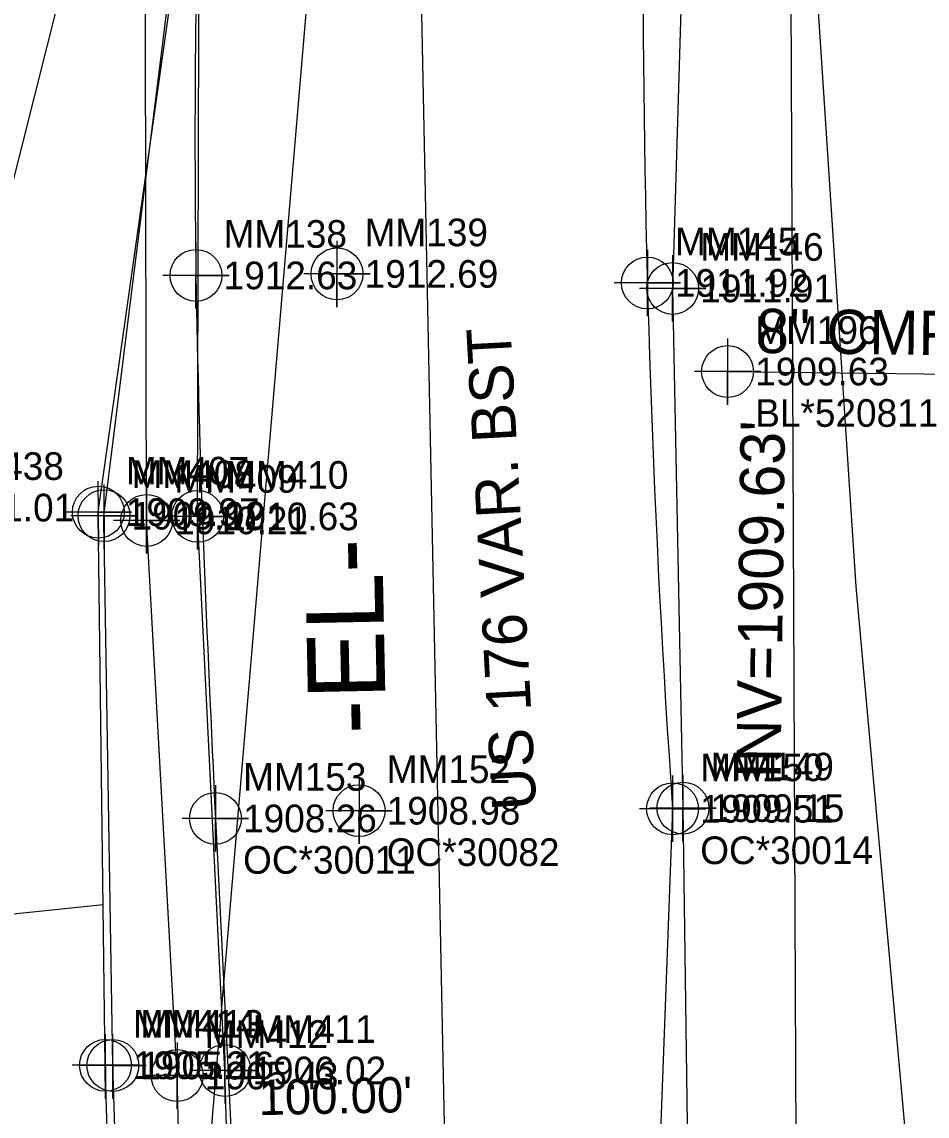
# Model space of a CAD drawing. Extents: x 1004514 to 1005247, y 553695 to 554706.
# Drawn here: x 1004985.3 to 1005067.1, y 554027.6 to 554126.5 of the extents above; entities that cross this region are included whole.
import ezdxf

# ---------------------------------------------------------------- set-up
doc = ezdxf.new("R2010")
doc.units = 0
for name, color, linetype in [('COGO Default Chain', 7, 'Continuous'), ('Default Symbol Cogo Elevation', 7, 'Continuous'), ('Default Symbol Cogo Number', 7, 'Continuous'), ('Exist DTM Crownline Cogo Comment', 7, 'Continuous'), ('Exist DTM Crownline Cogo Elevation', 7, 'Continuous'), ('Exist DTM Crownline Cogo Number', 7, 'Continuous'), ('Exist DTM Crownline Cogo Point CELL', 7, 'Continuous'), ('Exist Guardrail', 7, 'Continuous'), ('Exist Guardrail Cogo Elevation', 7, 'Continuous'), ('Exist Guardrail Cogo Number', 7, 'Continuous'), ('Exist Guardrail Cogo Point CELL', 7, 'Continuous'), ('Exist Horizontal Alignment', 7, 'Continuous'), ('Exist Horizontal Alignment Direction Label', 7, 'Continuous'), ('Exist Right of Way Width CELL', 7, 'Continuous'), ('Exist Roads EOP', 7, 'Continuous'), ('Exist Roads EOP Cogo Comment', 7, 'Continuous'), ('Exist Roads EOP Cogo Elevation', 7, 'Continuous'), ('Exist Roads EOP Cogo Number', 7, 'Continuous'), ('Exist Roads EOP Cogo Point CELL', 7, 'Continuous'), ('Exist Roads EOP Text', 7, 'Continuous'), ('Exist Structure Minor Pipes CMP 8 Inch', 7, 'Continuous'), ('Exist Structure Minor Pipes CMP 8 Inch Cogo Comment', 7, 'Continuous'), ('Exist Structure Minor Pipes CMP 8 Inch Cogo Elevation', 7, 'Continuous'), ('Exist Structure Minor Pipes CMP 8 Inch Cogo Number', 7, 'Continuous'), ('Exist Structure Minor Pipes CMP 8 Inch Cogo Point CELL', 7, 'Continuous'), ('Exist Structure Minor Pipes CMP 8 Inch Invert', 7, 'Continuous'), ('Exist Structure Minor Pipes CMP 8 Inch Text', 7, 'Continuous'), ('Exist Utilities Telephone UG Conduit SUE LOS B', 7, 'Continuous'), ('Exist Utilities Telephone UG Conduit SUE LOS B Cogo Elevation', 7, 'Continuous'), ('Exist Utilities Telephone UG Conduit SUE LOS B Cogo Number', 7, 'Continuous'), ('Exist Utilities Telephone UG Conduit SUE LOS B Cogo Point CELL', 7, 'Continuous'), ('Exist Utilities Telephone UG Conduit SUE LOS B Leader', 7, 'Continuous'), ('Exist Utilities Telephone UG FO SUE LOS C', 7, 'Continuous'), ('Exist Utilities Telephone UG FO SUE LOS C Cogo Elevation', 7, 'Continuous'), ('Exist Utilities Telephone UG FO SUE LOS C Cogo Number', 7, 'Continuous'), ('Exist Utilities Telephone UG FO SUE LOS C Cogo Point CELL', 7, 'Continuous'), ('Exist Vegetation Woods Line', 7, 'Continuous'), ('Old_Level_3', 7, 'Continuous'), ('Scratch_Level_3', 7, 'Continuous')]:
    doc.layers.add(name, color=color, linetype=linetype)

msp = doc.modelspace()

# ---------------------------------------------------------------- linework, layer by layer
at = {"layer": 'COGO Default Chain'}
for p, q in [((1004974.9, 553701.543), (1005020.282, 554237.182)), ((1005024.623, 553970.464), (1005021.236, 554137.94))]:
    msp.add_line(p, q, dxfattribs=at)
at = {"layer": 'Exist DTM Crownline Cogo Point CELL'}
for points in [[(1005013.771, 554106.753), (1005013.771, 554100.753), (1005013.771, 554103.753), (1005016.771, 554103.753), (1005010.771, 554103.753)], [(1005015.769, 554058.214), (1005015.769, 554052.214), (1005015.769, 554055.214), (1005018.769, 554055.214), (1005012.769, 554055.214)]]:
    msp.add_lwpolyline(points, dxfattribs=at)
for centre in [(1005013.771, 554103.753), (1005015.769, 554055.214)]:
    msp.add_circle(centre, 2.344, dxfattribs=at)
at = {"layer": 'Exist Guardrail'}
msp.add_lwpolyline([(1005077.879, 554238.993), (1005058.749, 554204.287), (1005049.992, 554175.596), (1005045.293, 554142.756), (1005044.111, 554102.438), (1005045.04, 554055.452), (1005045.63, 554011.474), (1005045.274, 553965.154), (1005039.583, 553916.738), (1005028.889, 553873.019)], dxfattribs=at)
at = {"layer": 'Exist Guardrail Cogo Point CELL'}
for points in [[(1005044.111, 554105.438), (1005044.111, 554099.438), (1005044.111, 554102.438), (1005047.111, 554102.438), (1005041.111, 554102.438)], [(1005045.04, 554058.452), (1005045.04, 554052.452), (1005045.04, 554055.452), (1005048.04, 554055.452), (1005042.04, 554055.452)]]:
    msp.add_lwpolyline(points, dxfattribs=at)
for centre in [(1005044.111, 554102.438), (1005045.04, 554055.452)]:
    msp.add_circle(centre, 2.344, dxfattribs=at)
at = {"layer": 'Exist Horizontal Alignment'}
msp.add_line((1005024.623, 553970.464), (1005021.236, 554137.94), dxfattribs=at)
at = {"layer": 'Exist Roads EOP'}
for p, q in [((1005044.105, 554055.385), (1005042.505, 554012.793)), ((1005002.785, 554054.517), (1005004.922, 554011.456))]:
    msp.add_line(p, q, dxfattribs=at)
msp.add_ellipse((1006138.537, 554139.06), major_axis=(-344.807, -1052.019), ratio=0.99001, start_param=5.032146, end_param=5.10188, dxfattribs=at)
msp.add_spline([(1005026.381, 554243.671), (1005017.049, 554225.785), (1005004.478, 554185.698), (1005001.445, 554147.868), (1005001.025, 554103.612), (1005002.785, 554054.517)], degree=3, dxfattribs=at)
at = {"layer": 'Exist Roads EOP Cogo Point CELL'}
for points in [[(1005001.025, 554106.612), (1005001.025, 554100.612), (1005001.025, 554103.612), (1005004.025, 554103.612), (1004998.025, 554103.612)], [(1005041.827, 554105.929), (1005041.827, 554099.929), (1005041.827, 554102.929), (1005044.827, 554102.929), (1005038.827, 554102.929)], [(1005044.105, 554058.385), (1005044.105, 554052.385), (1005044.105, 554055.385), (1005047.105, 554055.385), (1005041.105, 554055.385)], [(1005002.785, 554057.517), (1005002.785, 554051.517), (1005002.785, 554054.517), (1005005.785, 554054.517), (1004999.785, 554054.517)]]:
    msp.add_lwpolyline(points, dxfattribs=at)
for centre in [(1005001.025, 554103.612), (1005041.827, 554102.929), (1005044.105, 554055.385), (1005002.785, 554054.517)]:
    msp.add_circle(centre, 2.344, dxfattribs=at)
at = {"layer": 'Exist Structure Minor Pipes CMP 8 Inch'}
msp.add_line((1005049.076, 554094.923), (1005071.127, 554094.65), dxfattribs=at)
at = {"layer": 'Exist Structure Minor Pipes CMP 8 Inch Cogo Point CELL'}
msp.add_lwpolyline([(1005049.076, 554097.923), (1005049.076, 554091.923), (1005049.076, 554094.923), (1005052.076, 554094.923), (1005046.076, 554094.923)], dxfattribs=at)
msp.add_circle((1005049.076, 554094.923), 2.344, dxfattribs=at)
at = {"layer": 'Exist Utilities Telephone UG Conduit SUE LOS B'}
for points in [[(1004986.625, 553881.898), (1004994.172, 553936.442), (1004994.355, 553983.339), (1004992.834, 554032.196), (1004992.187, 554082.209), (1005000.242, 554139.11), (1005002.91, 554167.939), (1005012.741, 554216.936), (1005031.231, 554265.036), (1005060.708, 554304.647)], [(1004986.909, 553881.957), (1004994.669, 553936.387), (1004995.066, 553983.404), (1004993.502, 554032.182), (1004992.704, 554081.89), (1004999.846, 554139.17), (1005002.6, 554167.938), (1005012.391, 554217.264), (1005034.093, 554264.981), (1005060.823, 554304.66)], [(1004996.466, 553880.309), (1005003.636, 553934.419), (1005005.075, 553983.38), (1005003.635, 554031.726), (1005001.159, 554081.826), (1005001.307, 554137.229), (1005005.127, 554167.881), (1005016.898, 554214.508), (1005037.162, 554252.759), (1005044.72, 554267.983), (1005066.683, 554300.275)]]:
    msp.add_lwpolyline(points, dxfattribs=at)
at = {"layer": 'Exist Utilities Telephone UG Conduit SUE LOS B Cogo Point CELL'}
for points in [[(1004992.171, 554085.024), (1004992.204, 554079.209), (1004992.187, 554082.209), (1004995.204, 554082.209), (1004989.204, 554082.209)], [(1004992.688, 554084.704), (1004992.721, 554078.89), (1004992.704, 554081.89), (1004995.721, 554081.89), (1004989.721, 554081.89)], [(1005001.143, 554084.641), (1005001.176, 554078.826), (1005001.159, 554081.826), (1005004.176, 554081.826), (1004998.176, 554081.826)], [(1004992.819, 554035.01), (1004992.852, 554029.196), (1004992.834, 554032.196), (1004995.852, 554032.196), (1004989.852, 554032.196)], [(1004993.486, 554034.997), (1004993.519, 554029.182), (1004993.502, 554032.182), (1004996.519, 554032.182), (1004990.519, 554032.182)], [(1005003.619, 554034.541), (1005003.652, 554028.726), (1005003.635, 554031.726), (1005006.652, 554031.726), (1005000.652, 554031.726)]]:
    msp.add_lwpolyline(points, dxfattribs=at)
for centre in [(1004992.204, 554082.209), (1004992.721, 554081.89), (1005001.176, 554081.826), (1004992.852, 554032.196), (1004993.519, 554032.182), (1005003.652, 554031.726)]:
    msp.add_circle(centre, 2.344, dxfattribs=at)
at = {"layer": 'Exist Utilities Telephone UG Conduit SUE LOS B Leader'}
msp.add_line((1004992.647, 554046.707), (1004963.772, 554043.71), dxfattribs=at)
at = {"layer": 'Exist Utilities Telephone UG FO SUE LOS C'}
msp.add_lwpolyline([(1004993.352, 553880.974), (1004999.906, 553935.306), (1005000.501, 553983.286), (1004999.325, 554031.271), (1004996.571, 554081.46), (1004996.427, 554140.051), (1004998.713, 554168.32), (1005009.154, 554220.252), (1005037.109, 554266.749), (1005065.185, 554302.194)], dxfattribs=at)
at = {"layer": 'Exist Utilities Telephone UG FO SUE LOS C Cogo Point CELL'}
for points in [[(1004996.571, 554084.46), (1004996.571, 554078.46), (1004996.571, 554081.46), (1004999.571, 554081.46), (1004993.571, 554081.46)], [(1004999.325, 554034.271), (1004999.325, 554028.271), (1004999.325, 554031.271), (1005002.325, 554031.271), (1004996.325, 554031.271)]]:
    msp.add_lwpolyline(points, dxfattribs=at)
for centre in [(1004996.571, 554081.46), (1004999.325, 554031.271)]:
    msp.add_circle(centre, 2.344, dxfattribs=at)
at = {"layer": 'Exist Vegetation Woods Line'}
msp.add_lwpolyline([(1005043.245, 553870.571), (1005060.795, 553939.084), (1005067.553, 553999.387), (1005060.697, 554075.478), (1005056.834, 554134.404), (1005061.711, 554166.622), (1005070.29, 554196.972), (1005092.518, 554231.451), (1005101.443, 554246.608), (1005128.922, 554275.434)], dxfattribs=at)
at = {"layer": 'Old_Level_3'}
msp.add_line((1005054.705, 554152.316), (1005055.501, 553967.61), dxfattribs=at)
at = {"layer": 'Scratch_Level_3'}
msp.add_line((1004952.617, 553985.711), (1005030.054, 554292.752), dxfattribs=at)

# ---------------------------------------------------------------- texts
at = {"layer": 'Default Symbol Cogo Elevation'}
msp.add_text('1951.01', height=2.5, dxfattribs=at).set_placement((1004977.938, 554081.373))
at = {"layer": 'Default Symbol Cogo Number'}
msp.add_text('MM438', height=2.5, dxfattribs=at).set_placement((1004977.938, 554085.123))
at = {"layer": 'Exist DTM Crownline Cogo Comment'}
msp.add_text('OC*30082', height=2.5, dxfattribs=at).set_placement((1005018.269, 554050.214))
at = {"layer": 'Exist DTM Crownline Cogo Elevation'}
for s, p in [('1912.69', (1005016.271, 554102.503)), ('1908.98', (1005018.269, 554053.964))]:
    msp.add_text(s, height=2.5, dxfattribs=at).set_placement(p)
at = {"layer": 'Exist DTM Crownline Cogo Number'}
for s, p in [('MM139', (1005016.271, 554106.253)), ('MM152', (1005018.269, 554057.714))]:
    msp.add_text(s, height=2.5, dxfattribs=at).set_placement(p)
at = {"layer": 'Exist Guardrail Cogo Elevation'}
for s, p in [('1911.91', (1005046.611, 554101.188)), ('1909.15', (1005047.54, 554054.202))]:
    msp.add_text(s, height=2.5, dxfattribs=at).set_placement(p)
at = {"layer": 'Exist Guardrail Cogo Number'}
for s, p in [('MM146', (1005046.611, 554104.938)), ('MM149', (1005047.54, 554057.952))]:
    msp.add_text(s, height=2.5, dxfattribs=at).set_placement(p)
at = {"layer": 'Exist Horizontal Alignment Direction Label'}
msp.add_text('-EL-', height=7, rotation=91.15854, dxfattribs=at).set_placement((1005018.215, 554062.191))
at = {"layer": 'Exist Right of Way Width CELL'}
msp.add_text("100.00'", height=3.2, rotation=1.15854, dxfattribs=at).set_placement((1005006.713, 554027.684))
at = {"layer": 'Exist Roads EOP Cogo Comment'}
for s, p in [('OC*30014', (1005046.605, 554050.385)), ('OC*30011', (1005005.285, 554049.517))]:
    msp.add_text(s, height=2.5, dxfattribs=at).set_placement(p)
at = {"layer": 'Exist Roads EOP Cogo Elevation'}
for s, p in [('1912.63', (1005003.525, 554102.362)), ('1911.92', (1005044.327, 554101.679)), ('1909.51', (1005046.605, 554054.135)), ('1908.26', (1005005.285, 554053.267))]:
    msp.add_text(s, height=2.5, dxfattribs=at).set_placement(p)
at = {"layer": 'Exist Roads EOP Cogo Number'}
for s, p in [('MM138', (1005003.525, 554106.112)), ('MM145', (1005044.327, 554105.429)), ('MM150', (1005046.605, 554057.885)), ('MM153', (1005005.285, 554057.017))]:
    msp.add_text(s, height=2.5, dxfattribs=at).set_placement(p)
at = {"layer": 'Exist Roads EOP Text'}
msp.add_text('US 176 VAR. BST', height=4, rotation=93.07895, dxfattribs=at).set_placement((1005031.804, 554055.351))
at = {"layer": 'Exist Structure Minor Pipes CMP 8 Inch Cogo Comment'}
msp.add_text('BL*520811', height=2.5, dxfattribs=at).set_placement((1005051.576, 554089.923))
at = {"layer": 'Exist Structure Minor Pipes CMP 8 Inch Cogo Elevation'}
msp.add_text('1909.63', height=2.5, dxfattribs=at).set_placement((1005051.576, 554093.673))
at = {"layer": 'Exist Structure Minor Pipes CMP 8 Inch Cogo Number'}
msp.add_text('MM196', height=2.5, dxfattribs=at).set_placement((1005051.576, 554097.423))
at = {"layer": 'Exist Structure Minor Pipes CMP 8 Inch Invert'}
msp.add_text("INV=1909.63'", height=4, rotation=89.29734, dxfattribs=at).set_placement((1005053.863, 554058.082))
at = {"layer": 'Exist Structure Minor Pipes CMP 8 Inch Text'}
msp.add_text('8" CMP', height=4, rotation=359.29044, dxfattribs=at).set_placement((1005051.634, 554096.612))
at = {"layer": 'Exist Utilities Telephone UG Conduit SUE LOS B Cogo Elevation'}
for s, p in [('1909.97', (1004994.687, 554080.959)), ('1909.92', (1004995.204, 554080.64)), ('1910.63', (1005003.659, 554080.576)), ('1905.21', (1004995.334, 554030.946)), ('1905.16', (1004996.002, 554030.932)), ('1906.02', (1005006.135, 554030.476))]:
    msp.add_text(s, height=2.5, dxfattribs=at).set_placement(p)
at = {"layer": 'Exist Utilities Telephone UG Conduit SUE LOS B Cogo Number'}
for s, p in [('MM407', (1004994.687, 554084.709)), ('MM408', (1004995.204, 554084.39)), ('MM410', (1005003.659, 554084.326)), ('MM414', (1004995.334, 554034.696)), ('MM413', (1004996.002, 554034.682)), ('MM411', (1005006.135, 554034.226))]:
    msp.add_text(s, height=2.5, dxfattribs=at).set_placement(p)
at = {"layer": 'Exist Utilities Telephone UG FO SUE LOS C Cogo Elevation'}
for s, p in [('1910.21', (1004999.071, 554080.21)), ('1905.43', (1005001.825, 554030.021))]:
    msp.add_text(s, height=2.5, dxfattribs=at).set_placement(p)
at = {"layer": 'Exist Utilities Telephone UG FO SUE LOS C Cogo Number'}
for s, p in [('MM409', (1004999.071, 554083.96)), ('MM412', (1005001.825, 554033.771))]:
    msp.add_text(s, height=2.5, dxfattribs=at).set_placement(p)

doc.saveas('drawing.dxf')
